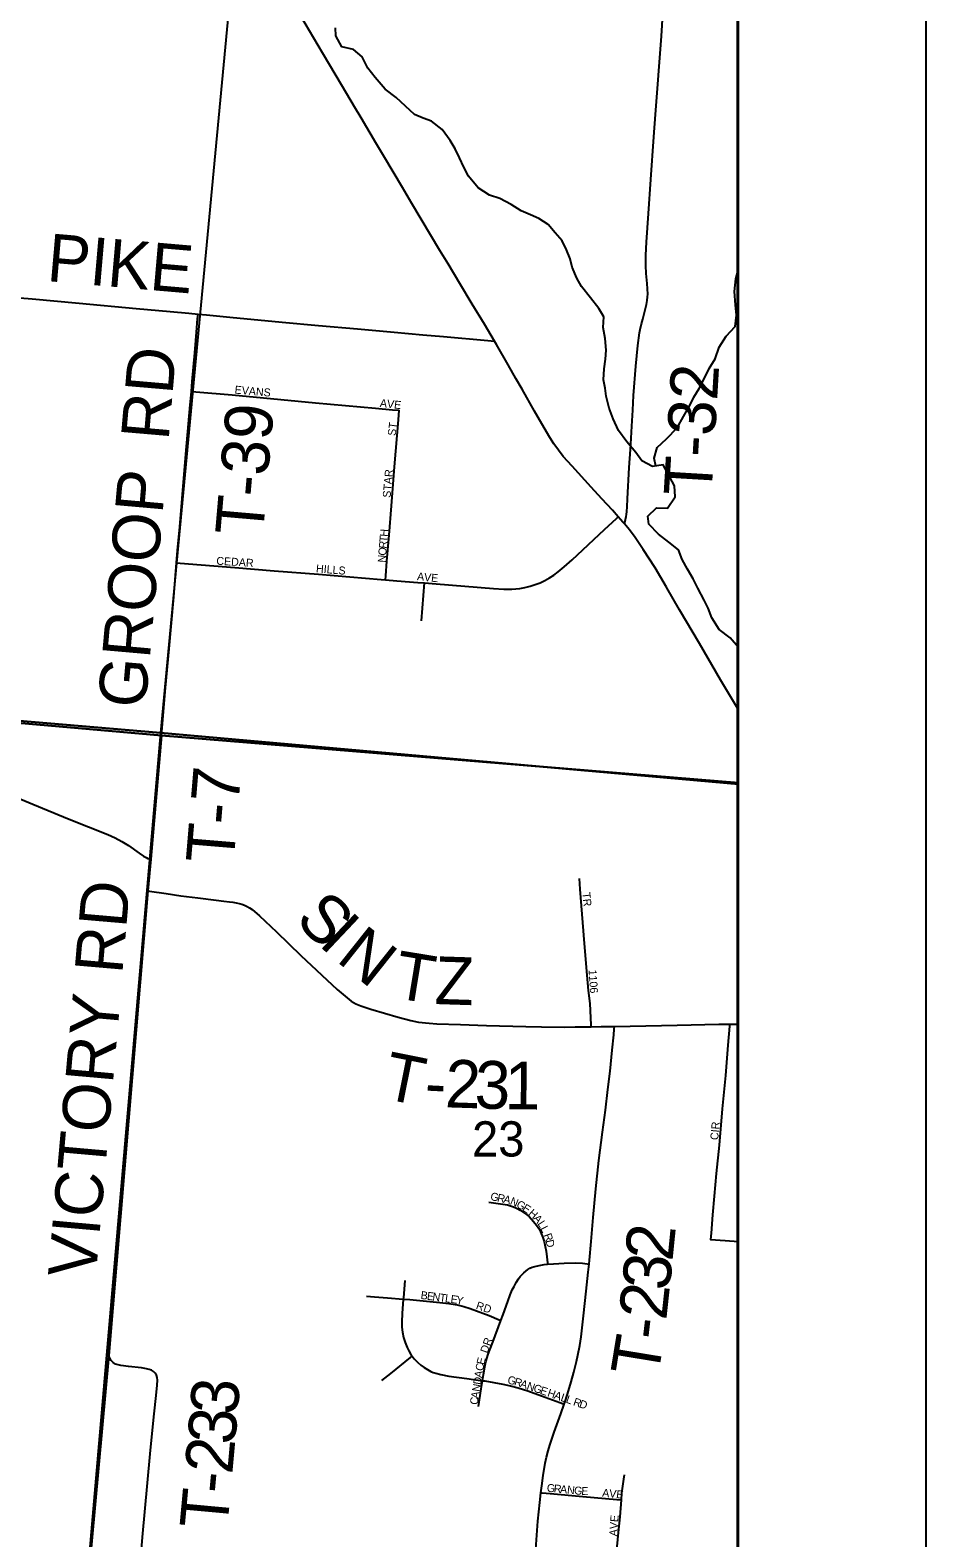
# Model space of a CAD drawing. Extents: x 0 to 680, y 0 to 440.
# Drawn here: x 271.86 to 288.52, y 322.85 to 350.9 of the extents above; entities that cross this region are included whole.
import ezdxf

# ---------------------------------------------------------------- set-up
doc = ezdxf.new("R2010")
doc.units = 0
for name, color, linetype in [('GM_X_Adjacent_County', 7, 'Continuous'), ('GM_X_County', 7, 'Continuous'), ('GM_X_County_Road', 7, 'Continuous'), ('GM_X_County_Road_Text', 7, 'Continuous'), ('GM_X_Minor_River', 7, 'Continuous'), ('GM_X_Section', 7, 'Continuous'), ('GM_X_Section_Text', 7, 'Continuous'), ('GM_X_Township', 7, 'Continuous'), ('GM_X_Township_Road', 7, 'Continuous'), ('GM_X_Township_Road_Text', 7, 'Continuous'), ('GM_X_Township_Subdivision', 7, 'Continuous'), ('GM_X_Township_Subdivision_Text', 7, 'Continuous'), ('SH_Data', 7, 'Continuous'), ('SH_Text', 7, 'Continuous')]:
    doc.layers.add(name, color=color, linetype=linetype)

msp = doc.modelspace()

# ---------------------------------------------------------------- linework, layer by layer
at = {"layer": 'GM_X_Adjacent_County'}
msp.add_lwpolyline([(285.035, 209.752), (285.035, 415.359), (154.698, 415.359)], dxfattribs=at)
at = {"layer": 'GM_X_County'}
msp.add_lwpolyline([(285.035, 209.752), (285.035, 415.359), (154.698, 415.359)], dxfattribs=at)
at = {"layer": 'GM_X_County_Road'}
for points in [[(280.496, 345.113), (280.311, 345.424), (280.086, 345.799), (279.856, 346.184), (279.636, 346.549), (279.485, 346.799), (278.96, 347.674), (278.787, 347.967), (278.44, 348.552), (278.29, 348.802), (278.019, 349.263), (277.896, 349.472), (277.671, 349.848), (277.302, 350.476), (276.98, 351.021), (276.702, 351.477), (276.527, 351.769), (276.352, 352.061), (275.981, 352.688), (275.754, 353.063), (275.573, 353.351), (275.505, 353.451)], [(259.507, 347.026), (259.795, 346.995), (260.279, 346.949), (260.715, 346.907), (261.442, 346.846), (262.023, 346.796), (262.721, 346.727), (263.621, 346.648), (264.783, 346.539), (265.219, 346.502), (265.751, 346.453), (266.864, 346.347), (267.654, 346.274), (268.947, 346.158), (269.576, 346.1), (270.497, 346.019), (271.368, 345.941), (271.902, 345.897), (272.773, 345.816), (273.838, 345.72), (274.466, 345.661), (274.814, 345.63)], [(274.814, 345.63), (274.985, 345.614)], [(274.985, 345.614), (275.146, 345.6), (275.58, 345.556), (276.548, 345.464), (277.226, 345.403), (277.952, 345.337), (278.63, 345.278), (279.163, 345.23), (279.55, 345.198), (280.374, 345.124), (280.496, 345.113)], [(282.799, 341.844), (282.693, 341.965), (282.497, 342.18), (282.298, 342.394), (281.941, 342.787), (281.777, 342.967), (281.687, 343.08), (281.604, 343.198), (281.525, 343.32), (281.377, 343.574), (281.243, 343.811), (281.014, 344.215), (280.897, 344.415), (280.751, 344.668), (280.534, 345.048), (280.496, 345.113)], [(282.914, 341.714), (282.886, 341.746), (282.799, 341.844)], [(283.703, 340.521), (283.696, 340.532), (283.485, 340.892), (283.263, 341.237), (283.117, 341.456), (283.009, 341.6), (282.914, 341.714)], [(285.035, 338.252), (284.701, 338.811), (284.312, 339.485), (283.94, 340.112), (283.703, 340.521)]]:
    msp.add_lwpolyline(points, dxfattribs=at)
at = {"layer": 'GM_X_Minor_River'}
for points in [[(285.035, 339.411), (284.88, 339.592), (284.674, 339.749), (284.54, 339.965), (284.471, 340.144), (284.395, 340.294), (284.279, 340.515), (284.192, 340.689), (284.088, 340.868), (283.989, 341.048), (283.92, 341.227), (283.743, 341.372), (283.549, 341.523), (283.367, 341.704), (283.351, 341.858), (283.513, 342.011), (283.715, 342.003), (283.861, 342.215), (283.845, 342.418), (283.723, 342.651), (283.636, 342.807), (283.44, 342.779), (283.239, 342.883), (283.128, 343.039), (282.958, 343.237), (282.806, 343.447), (282.708, 343.668), (282.633, 343.865), (282.576, 344.086), (282.554, 344.235), (282.526, 344.39), (282.541, 344.598), (282.561, 344.776), (282.575, 344.943), (282.554, 345.157), (282.521, 345.365), (282.529, 345.562), (282.442, 345.717), (282.284, 345.915), (282.114, 346.125), (282.027, 346.281), (281.946, 346.49), (281.906, 346.639), (281.837, 346.807), (281.756, 346.974), (281.627, 347.124), (281.498, 347.28), (281.321, 347.395), (281.167, 347.462), (280.996, 347.536), (280.807, 347.651), (280.6, 347.766), (280.405, 347.828), (280.198, 347.961), (280.017, 348.183), (279.93, 348.345), (279.849, 348.524), (279.767, 348.686), (279.674, 348.842), (279.528, 349.045), (279.328, 349.202), (279.174, 349.258), (279.008, 349.325), (278.844, 349.481), (278.673, 349.644), (278.467, 349.801), (278.28, 350.017), (278.145, 350.191), (278.04, 350.4), (277.876, 350.539), (277.662, 350.583), (277.546, 350.793), (277.542, 350.941)], [(283.496, 342.787), (283.471, 342.934), (283.521, 343.135), (283.696, 343.294), (283.895, 343.5), (284.016, 343.712), (284.132, 343.913), (284.205, 344.067), (284.302, 344.227), (284.387, 344.386), (284.491, 344.599), (284.6, 344.782), (284.674, 345.001), (284.808, 345.202), (284.976, 345.384), (284.997, 345.592), (284.982, 345.789), (284.961, 346.033), (284.988, 346.27), (285.035, 346.448)]]:
    msp.add_lwpolyline(points, dxfattribs=at)
at = {"layer": 'GM_X_Section'}
for points in [[(260.527, 354.766), (275.758, 353.416), (274.289, 337.825), (258.466, 339.173)], [(285.035, 336.872), (285.035, 352.57), (275.758, 353.416), (274.289, 337.825)], [(258.466, 339.173), (274.289, 337.825), (272.932, 322.173), (257.365, 323.612)], [(285.035, 321.065), (285.035, 336.872), (274.289, 337.825), (272.932, 322.173)]]:
    msp.add_lwpolyline(points, close=True, dxfattribs=at)
at = {"layer": 'GM_X_Township'}
for points in [[(243.787, 340.531), (258.485, 339.173), (267.813, 338.347), (274.304, 337.773), (285.035, 336.894), (285.035, 415.359)], [(272.949, 322.12), (273.328, 326.241), (274.05, 334.886), (274.105, 335.472), (274.304, 337.773), (267.813, 338.347), (258.485, 339.173), (243.787, 340.531), (228.078, 341.882), (225.071, 342.231), (204.178, 344.406)], [(285.035, 308.609), (285.035, 336.894), (274.304, 337.773), (274.105, 335.472), (274.05, 334.886), (273.328, 326.241), (272.949, 322.12)]]:
    msp.add_lwpolyline(points, dxfattribs=at)
at = {"layer": 'GM_X_Township_Road'}
msp.add_line((284.876, 332.404), (285.035, 332.406), dxfattribs=at)
for points in [[(283.033, 343.194), (283.053, 343.532), (283.069, 343.827), (283.085, 344.098), (283.128, 344.646), (283.146, 344.838), (283.166, 345.031), (283.195, 345.264), (283.208, 345.33), (283.232, 345.433), (283.256, 345.521), (283.291, 345.642), (283.316, 345.744), (283.327, 345.795), (283.338, 345.867), (283.346, 345.935), (283.348, 345.985), (283.346, 346.083), (283.336, 346.181), (283.317, 346.371), (283.315, 346.515), (283.315, 346.709), (283.328, 346.951), (283.365, 347.485), (283.404, 348.116), (283.459, 348.913), (283.495, 349.329), (283.602, 350.784), (283.65, 351.512)], [(274.861, 344.176), (274.877, 344.363), (274.924, 344.894), (274.955, 345.281), (274.977, 345.523), (274.985, 345.614)], [(274.586, 340.987), (274.605, 341.219), (274.645, 341.654), (274.692, 342.186), (274.758, 343.008), (274.838, 343.928), (274.861, 344.176)], [(282.914, 341.714), (282.933, 341.795), (282.946, 341.848), (282.953, 341.884), (282.961, 341.943), (282.964, 342.027), (282.973, 342.176), (283.005, 342.759), (283.027, 343.096), (283.033, 343.194)], [(274.304, 337.773), (274.383, 338.662), (274.449, 339.387), (274.533, 340.354), (274.586, 340.987)], [(274.105, 335.472), (274.129, 335.743), (274.154, 336.026), (274.193, 336.467), (274.242, 337.061), (274.284, 337.536), (274.304, 337.773)], [(271.509, 336.664), (272.093, 336.421), (272.587, 336.217), (272.95, 336.076), (273.311, 335.932), (273.443, 335.872), (273.57, 335.804), (273.693, 335.727), (273.891, 335.585), (273.973, 335.532), (274.023, 335.503), (274.053, 335.489), (274.08, 335.478), (274.105, 335.472)], [(274.05, 334.886), (274.105, 335.472)], [(273.326, 326.271), (273.324, 326.292), (273.327, 326.438), (273.342, 326.632), (273.402, 327.31), (273.522, 328.713), (273.581, 329.391), (273.651, 330.165), (273.75, 331.278), (273.818, 332.101), (273.871, 332.775), (273.913, 333.258), (273.991, 334.178), (274.038, 334.759), (274.05, 334.886)], [(274.05, 334.886), (274.085, 334.881), (274.396, 334.837), (274.666, 334.795), (274.982, 334.755), (275.325, 334.711), (275.465, 334.694), (275.568, 334.682), (275.631, 334.674), (275.692, 334.663), (275.748, 334.651), (275.802, 334.636), (275.852, 334.619), (275.899, 334.596), (275.943, 334.57), (275.993, 334.537), (276.131, 334.419), (276.444, 334.122), (276.896, 333.681), (277.285, 333.314), (277.571, 333.051), (277.719, 332.924), (277.836, 332.835), (277.92, 332.783), (278.011, 332.743), (278.196, 332.683), (278.71, 332.536), (278.944, 332.471), (279.087, 332.44), (279.282, 332.421), (279.428, 332.411), (279.864, 332.399), (280.35, 332.383), (281.079, 332.361), (281.37, 332.356), (281.807, 332.349), (282.001, 332.353), (282.219, 332.355), (282.298, 332.357)], [(282.259, 327.941), (282.266, 328.016), (282.297, 328.363), (282.336, 328.806), (282.384, 329.34), (282.442, 329.867), (282.507, 330.398), (282.561, 330.808), (282.607, 331.188), (282.647, 331.533), (282.69, 331.921), (282.719, 332.204), (282.726, 332.31), (282.729, 332.363)], [(282.298, 332.357), (282.483, 332.359)], [(282.483, 332.359), (282.63, 332.362), (282.729, 332.363)], [(282.729, 332.363), (283.019, 332.368), (283.311, 332.374), (283.894, 332.386), (284.672, 332.402), (284.876, 332.404)], [(281.794, 325.335), (281.818, 325.404), (281.877, 325.586), (281.925, 325.749), (281.974, 325.934), (282.022, 326.128), (282.049, 326.248), (282.083, 326.427), (282.111, 326.589), (282.155, 326.98), (282.202, 327.44), (282.243, 327.79), (282.259, 327.941)], [(273.91, 322.353), (273.962, 322.933), (274.04, 323.804), (274.101, 324.482), (274.167, 325.158), (274.204, 325.496), (274.223, 325.689), (274.229, 325.785), (274.225, 325.831), (274.212, 325.874), (274.189, 325.912), (274.157, 325.944), (274.118, 325.967), (274.075, 325.983), (274.029, 325.994), (273.934, 326.009), (273.692, 326.034), (273.547, 326.054), (273.498, 326.065), (273.451, 326.083), (273.407, 326.11), (273.37, 326.146), (273.343, 326.191), (273.328, 326.241), (273.326, 326.271)], [(281.361, 323.688), (281.376, 323.816), (281.403, 324.009), (281.439, 324.236), (281.463, 324.347), (281.496, 324.466), (281.529, 324.571), (281.611, 324.812), (281.733, 325.158), (281.794, 325.335)], [(281.189, 321.447), (281.191, 321.489), (281.21, 321.8), (281.25, 322.38), (281.302, 323.162), (281.339, 323.509), (281.361, 323.688)]]:
    msp.add_lwpolyline(points, dxfattribs=at)
at = {"layer": 'GM_X_Township_Subdivision'}
for points in [[(274.861, 344.176), (274.943, 344.169), (275.622, 344.111), (276.202, 344.055), (277.17, 343.966), (278.283, 343.865), (278.605, 343.836), (278.727, 343.826)], [(278.473, 340.672), (278.478, 340.743), (278.498, 341.016), (278.538, 341.502), (278.582, 342.049), (278.642, 342.775), (278.715, 343.646), (278.727, 343.826)], [(279.194, 340.614), (279.411, 340.596), (280.479, 340.507), (280.674, 340.497), (280.822, 340.499), (280.968, 340.511), (281.065, 340.527), (281.161, 340.55), (281.255, 340.581), (281.346, 340.617), (281.435, 340.659), (281.521, 340.706), (281.604, 340.759), (281.684, 340.817), (281.797, 340.91), (281.942, 341.042), (282.544, 341.608), (282.765, 341.812), (282.799, 341.844)], [(274.586, 340.987), (274.654, 340.981), (275.673, 340.9), (276.401, 340.84), (277.227, 340.774), (278.392, 340.679), (278.473, 340.672)], [(278.473, 340.672), (278.683, 340.655), (279.071, 340.624), (279.194, 340.614)], [(279.144, 339.906), (279.194, 340.614)], [(282.298, 332.357), (282.296, 332.395), (282.29, 332.525), (282.276, 332.788), (282.25, 333.034), (282.22, 333.314), (282.175, 333.907), (282.141, 334.294), (282.091, 334.917), (282.078, 335.115)], [(284.876, 332.404), (284.872, 332.369), (284.841, 332.016), (284.793, 331.452), (284.733, 330.83), (284.674, 330.153), (284.624, 329.63), (284.585, 329.204), (284.555, 328.86), (284.528, 328.517), (284.518, 328.399), (284.791, 328.381), (285.035, 328.362)], [(280.395, 329.095), (280.654, 329.058), (280.738, 329.042), (280.798, 329.024), (280.853, 329.004), (280.91, 328.981), (280.974, 328.945), (281.04, 328.904), (281.094, 328.863), (281.142, 328.824), (281.18, 328.785), (281.224, 328.735), (281.279, 328.663), (281.323, 328.601), (281.353, 328.542), (281.397, 328.439), (281.421, 328.359), (281.442, 328.27), (281.458, 328.184), (281.472, 328.078), (281.483, 327.966), (281.486, 327.939)], [(280.618, 326.893), (280.661, 327.005), (280.746, 327.245), (280.792, 327.37), (280.829, 327.461), (280.862, 327.526), (280.901, 327.598), (280.945, 327.668), (280.979, 327.711), (281.011, 327.747), (281.044, 327.781), (281.08, 327.811), (281.118, 327.839), (281.159, 327.863), (281.202, 327.882), (281.247, 327.898), (281.329, 327.917), (281.42, 327.933), (281.486, 327.939)], [(281.486, 327.939), (281.599, 327.949), (281.793, 327.959), (282.014, 327.963), (282.134, 327.956), (282.225, 327.945), (282.259, 327.941)], [(278.83, 327.634), (278.804, 327.315), (278.802, 327.289)], [(278.119, 327.343), (278.265, 327.332), (278.506, 327.312), (278.802, 327.289)], [(278.802, 327.289), (278.782, 327.021), (278.775, 326.869), (278.778, 326.771), (278.787, 326.673), (278.805, 326.576), (278.835, 326.482), (278.873, 326.391), (278.906, 326.326), (278.944, 326.262), (278.967, 326.231)], [(278.802, 327.289), (278.923, 327.28), (279.485, 327.23), (279.649, 327.208), (279.804, 327.182), (279.928, 327.154), (280.049, 327.113), (280.399, 326.983), (280.586, 326.906), (280.618, 326.893)], [(280.275, 325.773), (280.292, 325.885), (280.319, 326.031), (280.34, 326.124), (280.382, 326.263), (280.465, 326.49), (280.618, 326.893)], [(278.404, 325.777), (278.57, 325.904), (278.938, 326.207), (278.967, 326.231)], [(278.967, 326.231), (279.002, 326.182), (279.035, 326.146), (279.071, 326.111), (279.128, 326.064), (279.188, 326.021), (279.254, 325.978), (279.315, 325.946), (279.361, 325.926), (279.407, 325.91), (279.503, 325.885), (279.647, 325.859), (279.984, 325.813), (280.275, 325.773)], [(280.199, 325.292), (280.253, 325.624), (280.275, 325.773)], [(280.275, 325.773), (280.32, 325.767), (280.654, 325.709), (280.796, 325.678), (280.936, 325.641), (281.12, 325.583), (281.438, 325.464), (281.711, 325.364), (281.794, 325.335)], [(282.858, 323.555), (282.869, 323.683), (282.889, 323.857), (282.902, 323.941), (282.919, 324.021)], [(281.361, 323.688), (281.384, 323.686), (281.536, 323.672), (282.141, 323.619), (282.773, 323.563), (282.858, 323.555)], [(282.643, 321.309), (282.646, 321.351), (282.673, 321.655), (282.717, 322.028), (282.747, 322.315), (282.769, 322.559), (282.805, 322.95), (282.833, 323.243), (282.858, 323.555)]]:
    msp.add_lwpolyline(points, dxfattribs=at)
at = {"layer": 'SH_Data'}
for p, q in [((288.52, 418.859), (288.52, 173.859)), ((285.02, 415.359), (285.02, 177.359))]:
    msp.add_line(p, q, dxfattribs=at)
at = {"layer": 'SH_Text'}
for points in [[(47.02, 415.359), (285.02, 415.359), (285.02, 177.359), (47.02, 177.359)], [(285.019, 415.359), (47.02, 415.359), (47.02, 177.359), (285.019, 177.359)]]:
    msp.add_lwpolyline(points, close=True, dxfattribs=at)

# ---------------------------------------------------------------- texts
at = {"layer": 'GM_X_County_Road_Text'}
msp.add_text('PIKE', height=0.8894, rotation=355.0567, dxfattribs=at).set_placement((272.157, 346.23))
at = {"layer": 'GM_X_Section_Text'}
msp.add_text('23', height=0.6552, rotation=0, dxfattribs=at).set_placement((280.081, 329.943))
at = {"layer": 'GM_X_Township_Road_Text'}
for s, height, rotation, p in [('RD', 0.8894, 85.1131, (274.437, 343.249)), ('T-32', 0.8894, 86.5979, (284.532, 342.214)), ('T-39', 0.8894, 85.0756, (276.189, 341.47)), ('GROOP', 0.8894, 84.9678, (274.006, 338.266)), ('T-7', 0.8894, 85.2348, (275.644, 335.372)), ('RD', 0.8894, 85.0738, (273.576, 333.324)), ('S', 0.889, 315.9431, (276.767, 334.318)), ('I', 0.889, 316.6682, (277.21, 333.889)), ('N', 0.889, 321.4964, (277.535, 333.587)), ('T', 0.889, 350.666, (278.597, 332.9)), ('Z', 0.889, 358.1557, (279.378, 332.78)), ('VICTORY', 0.8894, 84.9299, (273.08, 327.663)), ('T', 0.889, 348.5674, (278.393, 331.028)), ('2', 0.889, 358.1401, (279.57, 330.859)), ('3', 0.889, 358.2342, (280.12, 330.841)), ('1', 0.889, 359.3626, (280.686, 330.824)), ('-', 0.889, 357.079, (279.188, 330.878)), ('2', 0.889, 84.2405, (283.807, 327.98)), ('3', 0.889, 84.161, (283.751, 327.433)), ('2', 0.889, 83.8232, (283.692, 326.883)), ('-', 0.889, 83.2797, (283.648, 326.511)), ('T', 0.889, 80.6807, (283.534, 325.811)), ('3', 0.889, 85.5296, (275.719, 325.122)), ('3', 0.889, 84.9875, (275.671, 324.567)), ('2', 0.889, 84.8157, (275.621, 324.019)), ('-', 0.889, 84.7599, (275.587, 323.654)), ('T', 0.889, 84.7555, (275.527, 322.992))]:
    msp.add_text(s, height=height, rotation=rotation, dxfattribs=at).set_placement(p)
at = {"layer": 'GM_X_Township_Subdivision_Text'}
for s, height, rotation, p in [('EVANS', 0.1482, 355.0284, (275.662, 344.136)), ('AVE', 0.1482, 353.8867, (278.362, 343.888)), ('ST', 0.1482, 82.8666, (278.658, 343.342)), ('STAR', 0.1482, 85.028, (278.566, 342.193)), ('R', 0.148, 85.1375, (278.494, 341.247)), ('T', 0.148, 85.1258, (278.504, 341.364)), ('H', 0.148, 85.1389, (278.513, 341.468)), ('CEDAR', 0.1482, 356.3452, (275.322, 340.953)), ('N', 0.148, 86.151, (278.475, 340.988)), ('O', 0.148, 85.1855, (278.483, 341.117)), ('HILLS', 0.1482, 355.3312, (277.175, 340.81)), ('A', 0.148, 353.9567, (279.054, 340.666)), ('V', 0.148, 353.9567, (279.183, 340.652)), ('E', 0.148, 354.5167, (279.315, 340.638)), ('TR', 0.1482, 276.3375, (282.13, 334.85)), ('1106', 0.1482, 273.9501, (282.248, 333.414)), ('CIR', 0.1482, 85.0327, (284.658, 330.244)), ('G', 0.148, 348.4457, (280.413, 329.135)), ('R', 0.148, 348.4328, (280.54, 329.108)), ('A', 0.148, 346.4779, (280.654, 329.085)), ('N', 0.148, 337.9956, (280.775, 329.056)), ('G', 0.148, 330.5696, (280.892, 329.01)), ('E', 0.148, 326.8707, (281.003, 328.947)), ('H', 0.148, 317.9218, (281.117, 328.87)), ('A', 0.148, 310.7459, (281.21, 328.786)), ('L', 0.148, 302.5383, (281.292, 328.692)), ('L', 0.148, 296.785, (281.346, 328.607)), ('R', 0.148, 290.4395, (281.409, 328.483)), ('D', 0.148, 282.7587, (281.448, 328.378)), ('B', 0.148, 352.4503, (279.119, 327.295)), ('E', 0.148, 352.4499, (279.236, 327.28)), ('N', 0.148, 352.4386, (279.339, 327.266)), ('T', 0.148, 352.4499, (279.469, 327.249)), ('L', 0.148, 352.4379, (279.572, 327.235)), ('E', 0.148, 352.1905, (279.675, 327.221)), ('Y', 0.148, 348.9816, (279.777, 327.208)), ('RD', 0.1482, 341.5651, (280.142, 327.111)), ('DR', 0.1482, 70.5566, (280.368, 326.273)), ('E', 0.148, 76.7391, (280.307, 326.059)), ('A', 0.148, 80.6239, (280.267, 325.817)), ('C', 0.148, 80.639, (280.288, 325.946)), ('N', 0.148, 80.6239, (280.224, 325.56)), ('D', 0.148, 80.6366, (280.246, 325.689)), ('G', 0.148, 343.5562, (280.728, 325.729)), ('R', 0.148, 342.9705, (280.853, 325.693)), ('A', 0.148, 341.3784, (280.964, 325.659)), ('N', 0.148, 341.0328, (281.087, 325.617)), ('G', 0.148, 341.0588, (281.211, 325.575)), ('E', 0.148, 341.0207, (281.334, 325.532)), ('C', 0.148, 80.6335, (280.184, 325.316)), ('A', 0.148, 80.6366, (280.203, 325.431)), ('H', 0.148, 341.0535, (281.47, 325.486)), ('A', 0.148, 341.0535, (281.593, 325.443)), ('L', 0.148, 341.0466, (281.717, 325.401)), ('L', 0.148, 341.0466, (281.815, 325.367)), ('R', 0.148, 341.0419, (281.951, 325.32)), ('D', 0.148, 341.0373, (282.062, 325.282)), ('G', 0.148, 354.6374, (281.467, 323.708)), ('R', 0.148, 354.6253, (281.596, 323.696)), ('A', 0.148, 354.6312, (281.713, 323.685)), ('N', 0.148, 354.6156, (281.843, 323.673)), ('G', 0.148, 354.6312, (281.973, 323.661)), ('E', 0.148, 357.643, (282.111, 323.648)), ('A', 0.148, 354.396, (282.497, 323.617)), ('V', 0.148, 354.417, (282.627, 323.604)), ('E', 0.148, 352.6581, (282.755, 323.592)), ('AVE', 0.1482, 86.0569, (282.78, 322.874))]:
    msp.add_text(s, height=height, rotation=rotation, dxfattribs=at).set_placement(p)

doc.saveas('drawing.dxf')
